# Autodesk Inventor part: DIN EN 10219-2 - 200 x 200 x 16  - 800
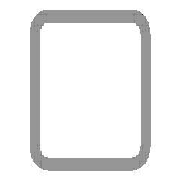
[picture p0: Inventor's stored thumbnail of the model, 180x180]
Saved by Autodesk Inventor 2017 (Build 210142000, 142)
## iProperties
Created: 2017-11
Part Number: DIN EN 10219-2 - 200 x 200 x 16  - 800
Material: Steel, Mild
Description: Cold formed welded structural hollow sections of non-alloy and fine grain structural steel
Document SubType Name: Modeling
Standard: DIN
Designer: iusti
Standard Revision: 2006-07
Standards Organization: DIN
Language: en-US
Size Designation: 200 x 200 x 16
Categories: <MemberInstance><Categories><Category DisplayName="Structural Shapes" InternalName="089c4875-fa83-4c05-b084-43b9cc11f5ed" Mnemonic="GRDR"><CategoryParameter Dis
Stock Number: 200 x 200 x 16
Mass: 67053.1 g
Surface Area: 10890.8 cm^2
Volume: 8541.79 cm^3
Density: 7.85 g/cm^3
Appearance: Semi-Polished
G_L: 800.000 mm
G_W: 200.000 mm
G_H: 200.000 mm
+A639C769-3126-41A6-9F80-CB71605C9A57+CUTDETAIL1: Cut
+C3782257-2068-46F1-A1C7-ECFA59CBB29E+CUTDETAIL2: Cut
IsCustomPart: 1
_CCFamilyMember: 103
_CCFamilyDisplayName: DIN EN 10219-2 (Square Hollow Section - Cold Formed) - Cold formed welded structural hollow sections of non-alloy and fine grain structural steel
_FrameMemberDoc: Frame Member File
_Version: 15.0.0
_GetPNFromCC: 1
Author: iusti
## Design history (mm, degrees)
node "Start plane"
node "End plane"
sketch "Sketch"
  geometry: L1 (-100, -52)-(-100, 52); L2 (-52, 100)-(52, 100); L3 (100, 52)-(100, -52); L4 (52, -100)-(-52, -100); L5 (-52, 84)-(52, 84); L6 (84, 52)-(84, -52); L7 (52, -84)-(-52, -84); L8 (-84, -52)-(-84, 52); L9 (0, 153.918)-(0, -153.918) reference; L10 (-153.918, 0)-(153.918, 0) reference; A1 r 48 centre (-52, -52) between (-100, -52) and (-52, -100); A2 r 48 centre (-52, 52) between (-52, 100) and (-100, 52); A3 r 48 centre (52, 52) between (100, 52) and (52, 100); A4 r 48 centre (52, -52) between (52, -100) and (100, -52); A5 r 32 centre (-52, 52) between (-52, 84) and (-84, 52); A6 r 32 centre (52, 52) between (84, 52) and (52, 84); A7 r 32 centre (52, -52) between (52, -84) and (84, -52); A8 r 32 centre (-52, -52) between (-84, -52) and (-52, -84)
  constraints: 16 end point, 16 point on circle, 8 centre point, 8 tangent, 4 parallel, 3 equal radius, 2 perpendicular, 7 other
  dimensions: "d7" = 48 radius of A1 (= G_IR); "d10" = 200 distance between parallel lines of L2 L4 (= G_H); "d11" = 200 distance between parallel lines of L1 L3 (= G_W); "d12" = 16 distance between parallel lines of L3 L6 (= G_T); "d15" = 100 distance between parallel lines of L2 L10 (= 0.5 x d10); "d16" = 100 distance between parallel lines of L9 L3 (= 0.5 x d11)
extrude "Body" new body sketch "Sketch" stored distance "d3" = 800 (= G_L); taper "d4" = 0 deg
node "Driven Length"
  sketch "Sketch3"
    geometry: L1 (0, 0)-(10, 0) reference
    constraints: 2 end point, 1 horizontal
  workplane "Work Plane3"
  sketch "Sketch4"
    geometry: L1 (-2, 100)-(12, 100) reference; L2 (-2, 900)-(12, 900) reference
    dimensions: "d18" = 800 distance between parallel lines of L1 L2 (derived)
workplane "Work Plane4"
split "Split1"
workplane "Work Plane5"
split "Split2"
body "Solid1"
other parameters: "G_W" = 200 [user parameter; used in 1 equation term], "G_H" = 200 [user parameter; used in 1 equation term], "G_T" = 16 [user parameter; used in 1 equation term], "G_IR" = 48 [user parameter; used in 1 equation term], "G_L" = 800 (= d18) [user parameter; used in 1 equation term], "d17" = 90 deg
